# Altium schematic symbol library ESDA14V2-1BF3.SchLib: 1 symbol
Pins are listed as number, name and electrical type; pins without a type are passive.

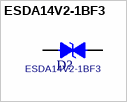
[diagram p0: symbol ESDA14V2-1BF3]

## ESDA14V2-1BF3
designator D?
footprint ST_CSP02N40P1x2_69x50x36
pins: A1, A2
